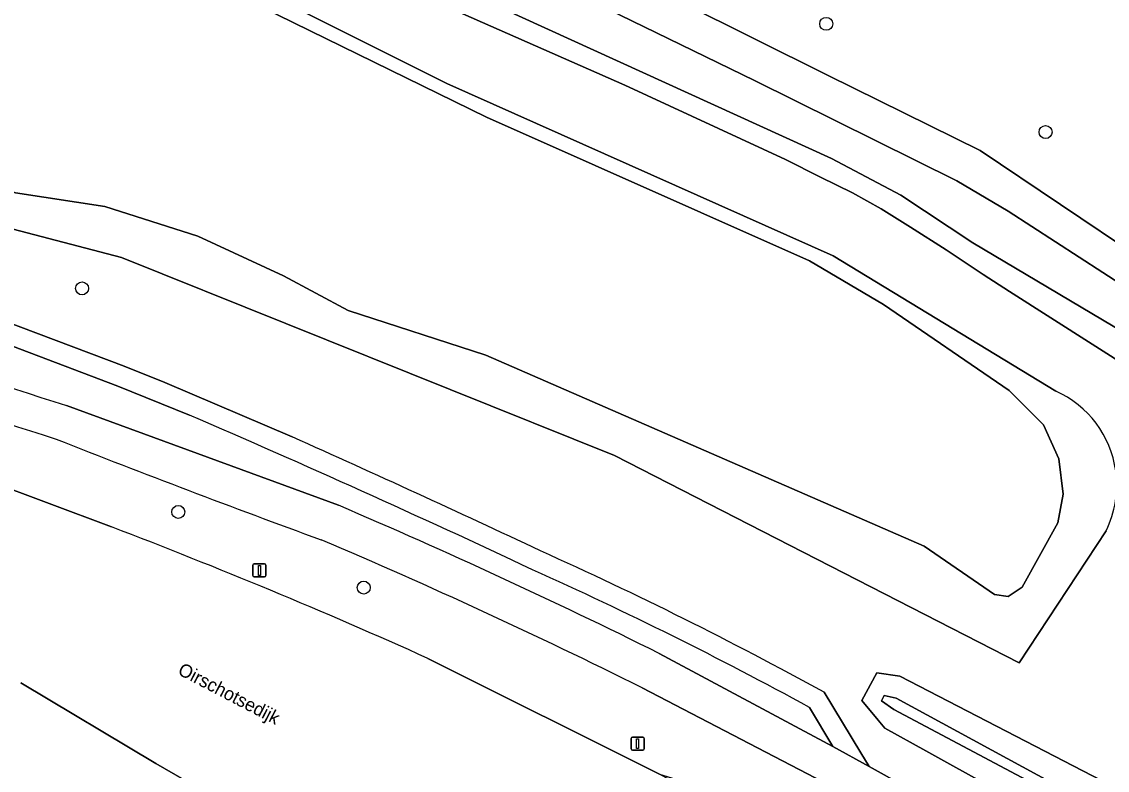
# Model space of a CAD drawing. Extents: x 156141 to 158132, y 385651 to 388333.
# Drawn here: x 157042.7 to 157124.7, y 386139.6 to 386196.1 of the extents above; entities that cross this region are included whole.
import ezdxf

# ---------------------------------------------------------------- set-up
doc = ezdxf.new("R2010")
doc.units = 0
for name, color, linetype in [('IMGEO_Berm_groen', 7, 'Continuous'), ('IMGEO_Boom', 7, 'Continuous'), ('IMGEO_Fietspad_gesloten', 7, 'Continuous'), ('IMGEO_Groenvoorziening', 7, 'Continuous'), ('IMGEO_Lichtmast', 7, 'Continuous'), ('IMGEO_Loofbos', 7, 'Continuous'), ('IMGEO_Oever', 7, 'Continuous'), ('IMGEO_Openbare_ruimte_label', 7, 'Continuous'), ('IMGEO_Rijbaan_lokaal_gesloten', 7, 'Continuous'), ('IMGEO_Voetpad_open', 7, 'Continuous'), ('IMGEO_Waterloop', 7, 'Continuous')]:
    doc.layers.add(name, color=color, linetype=linetype)

msp = doc.modelspace()

# ---------------------------------------------------------------- linework, layer by layer
at = {"layer": 'IMGEO_Berm_groen'}
for points in [[(157055.36, 386166.428), (157049.954, 386168.632), (157027.309, 386177.202)], [(157025.905, 386166.808), (157049.465, 386157.994)], [(157046.06, 386167.155), (157066.597, 386159.624)], [(157073.355, 386148.061), (157090.855, 386139.327), (157095.67, 386137.824), (157103.214, 386135.71), (157104.36, 386135.389), (157104.734, 386135.28), (157105.07, 386135.116), (157105.604, 386134.815), (157106.612, 386136.552), (157106.768, 386136.88), (157104.487, 386138.066), (157089.537, 386145.838)], [(157090.83, 386148.434), (157103.938, 386141.414), (157102.178, 386144.355)]]:
    msp.add_lwpolyline(points, dxfattribs=at)
for centre, radius, start, end in [((157167.479, 386548.294), 400.012, 247.70833, 252.32971), ((157171.751, 386565.051), 419.92, 248.03959, 252.47091), ((156726.52, 385402.107), 832.059, 64.764167, 66.72076), ((157336.91, 386902.288), 793.215, 248.428533, 249.976085), ((156888.445, 385741.984), 454.05, 63.52972, 66.89841), ((156893.257, 385748.601), 438.182, 65.73163, 69.11518), ((156888.764, 385742.679), 450.385, 63.52673, 66.92268), ((156959.162, 385882.983), 297.941, 61.31358, 65.80644)]:
    msp.add_arc(centre, radius, start, end, dxfattribs=at)
at = {"layer": 'IMGEO_Boom'}
for centre in [(157103.433, 386195.99), (157119.994, 386187.814), (157047.24, 386176.007), (157054.509, 386159.125), (157068.509, 386153.408)]:
    msp.add_circle(centre, 0.489, dxfattribs=at)
at = {"layer": 'IMGEO_Fietspad_gesloten'}
for points in [[(157066.597, 386159.624), (157046.06, 386167.155)], [(157106.669, 386139.896), (157103.938, 386141.414), (157090.83, 386148.434)], [(157089.537, 386145.838), (157104.487, 386138.066), (157106.768, 386136.88), (157129.321, 386124.103)], [(157134.922, 386123.988), (157116.672, 386134.337), (157106.669, 386139.896)]]:
    msp.add_lwpolyline(points, dxfattribs=at)
for centre, radius, start, end in [((157167.479, 386548.294), 400.012, 247.70833, 252.32971), ((157171.751, 386565.051), 419.92, 248.03959, 252.47091), ((157336.91, 386902.288), 793.215, 248.428533, 249.976085), ((156888.445, 385741.984), 454.05, 63.52972, 66.89841), ((156888.764, 385742.679), 450.385, 63.52673, 66.92268)]:
    msp.add_arc(centre, radius, start, end, dxfattribs=at)
at = {"layer": 'IMGEO_Groenvoorziening'}
for points in [[(157047.831, 386219.879), (157047.866, 386219.863), (157103.581, 386192.082), (157115.057, 386186.415), (157127.188, 386178.265), (157132.715, 386174.705), (157163.422, 386159.428)], [(157031.363, 386213.216), (157074.779, 386191.476), (157103.964, 386178.456), (157120.772, 386168.246)], [(157160.552, 386153.612), (157126.644, 386169.794), (157117.284, 386175.779), (157115.295, 386177.068), (157112.501, 386178.914), (157109.789, 386180.635), (157107.594, 386182.028), (157105.411, 386183.215), (157102.993, 386184.402), (157100.369, 386185.736), (157088.224, 386191.356), (157075.353, 386197.029)]]:
    msp.add_lwpolyline(points, dxfattribs=at)
msp.add_arc((157117.581, 386161.142), 7.788, 8.0112, 65.81079, dxfattribs=at)
at = {"layer": 'IMGEO_Lichtmast'}
for p, q in [((157060.239, 386155.211), (157061.029, 386155.211)), ((157061.029, 386155.211), (157060.239, 386155.211)), ((157060.139, 386154.311), (157060.139, 386155.111)), ((157060.139, 386155.111), (157060.139, 386154.311)), ((157061.129, 386155.111), (157061.129, 386154.311)), ((157061.129, 386154.311), (157061.129, 386155.111)), ((157061.029, 386154.211), (157060.239, 386154.211)), ((157060.239, 386154.211), (157061.029, 386154.211)), ((157088.797, 386142.12), (157089.587, 386142.12)), ((157089.587, 386142.12), (157088.797, 386142.12)), ((157088.697, 386141.22), (157088.697, 386142.02)), ((157088.697, 386142.02), (157088.697, 386141.22)), ((157089.687, 386142.02), (157089.687, 386141.22)), ((157089.687, 386141.22), (157089.687, 386142.02)), ((157089.587, 386141.12), (157088.797, 386141.12)), ((157088.797, 386141.12), (157089.587, 386141.12))]:
    msp.add_line(p, q, dxfattribs=at)
for points in [[(157060.559, 386155.086), (157060.709, 386155.086), (157060.709, 386154.336), (157060.559, 386154.336), (157060.559, 386155.086)], [(157089.117, 386141.995), (157089.267, 386141.995), (157089.267, 386141.245), (157089.117, 386141.245), (157089.117, 386141.995)]]:
    msp.add_lwpolyline(points, dxfattribs=at)
for centre, start, end in [((157060.239, 386155.111), 90, 180), ((157060.239, 386155.111), 90, 180), ((157061.029, 386155.111), 0, 90), ((157061.029, 386155.111), 360, 90), ((157060.239, 386154.311), 180, 270), ((157060.239, 386154.311), 180, 270), ((157061.029, 386154.311), 270, 0), ((157061.029, 386154.311), 270, 0), ((157088.797, 386142.02), 90, 180), ((157088.797, 386142.02), 90, 180), ((157089.587, 386142.02), 0, 90), ((157089.587, 386142.02), 360, 90), ((157088.797, 386141.22), 180, 270), ((157088.797, 386141.22), 180, 270), ((157089.587, 386141.22), 270, 0), ((157089.587, 386141.22), 270, 0)]:
    msp.add_arc(centre, 0.1, start, end, dxfattribs=at)
at = {"layer": 'IMGEO_Loofbos'}
for points in [[(157124.568, 386157.701), (157117.992, 386147.727), (157087.44, 386163.379), (157050.226, 386178.35), (157034.317, 386182.486), (157015.458, 386191.949), (157000, 386199.365), (156937.684, 386229.262), (156895.558, 386250), (156862.258, 386266.393), (156787.825, 386302.101), (156752.693, 386319.228)], [(157027.932, 386178.627), (157050.419, 386170.128), (157053.49, 386168.897), (157063.112, 386164.785)], [(157103.29, 386145.509), (157106.04, 386140.941), (157106.669, 386139.896), (157116.672, 386134.337), (157134.922, 386123.988), (157135.678, 386127.367), (157110.967, 386141.093), (157107.863, 386142.8), (157107.366, 386143.394), (157106.12, 386144.881), (157107.253, 386146.967), (157109.002, 386146.714), (157133.77, 386133.907), (157136.75, 386132.939), (157147.074, 386134.98), (157163.497, 386144.088), (157125.293, 386162.227)]]:
    msp.add_lwpolyline(points, dxfattribs=at)
for centre, radius, start, end in [((156638.121, 385213.343), 1042.046, 64.796612, 65.930582), ((157117.582, 386161.141), 7.787, 333.7823, 8.01641), ((156954.647, 385874.038), 309.501, 61.29718, 65.73109)]:
    msp.add_arc(centre, radius, start, end, dxfattribs=at)
at = {"layer": 'IMGEO_Oever'}
for points in [[(156752.693, 386319.228), (156787.825, 386302.101), (156862.258, 386266.393), (156895.558, 386250), (156937.684, 386229.262), (157000, 386199.365), (157015.458, 386191.949), (157034.317, 386182.486), (157050.226, 386178.35), (157087.44, 386163.379), (157117.992, 386147.727), (157124.568, 386157.701)], [(157006.157, 386224.026), (157077.773, 386188.944), (157102.176, 386178.077), (157107.75, 386174.799), (157117.258, 386168.288), (157119.834, 386165.712), (157121.005, 386163.136), (157121.333, 386160.466), (157120.911, 386158.312), (157118.242, 386153.44), (157117.164, 386152.738), (157116.134, 386152.878), (157110.841, 386156.532), (157077.726, 386170.958), (157067.328, 386174.33), (157062.457, 386176.953), (157055.993, 386179.951), (157048.968, 386182.199), (157042.223, 386183.23), (157036.79, 386185.197), (157030.139, 386188.007), (157000.911, 386201.778)], [(157163.422, 386159.428), (157132.715, 386174.705), (157127.188, 386178.265), (157115.057, 386186.415), (157103.581, 386192.082), (157047.866, 386219.863), (157047.831, 386219.879)], [(157120.772, 386168.246), (157103.964, 386178.456), (157074.779, 386191.476), (157031.363, 386213.216)], [(157056.353, 386212), (157098.016, 386191.719), (157113.285, 386184.131), (157117.173, 386181.836), (157129.679, 386173.733), (157130.1, 386172.843), (157129.726, 386171.86), (157128.93, 386171.579), (157127.524, 386171.719), (157114.503, 386179.447), (157109.07, 386183.054), (157103.824, 386185.817), (157078.766, 386197.246)], [(157075.353, 386197.029), (157088.224, 386191.356), (157100.369, 386185.736), (157102.993, 386184.402), (157105.411, 386183.215), (157107.594, 386182.028), (157109.789, 386180.635), (157112.501, 386178.914), (157115.295, 386177.068), (157117.284, 386175.779), (157126.644, 386169.794), (157160.552, 386153.612)]]:
    msp.add_lwpolyline(points, dxfattribs=at)
for points in [[(157170.409, 386143.435), (157169.335, 386145.238), (157168.117, 386146.206), (157167.302, 386146.245), (157163.497, 386144.088), (157147.074, 386134.98), (157136.75, 386132.939), (157133.77, 386133.907), (157109.002, 386146.714), (157107.253, 386146.967), (157106.12, 386144.881), (157107.366, 386143.394), (157107.863, 386142.8), (157110.967, 386141.093), (157135.678, 386127.367), (157138.716, 386127.281), (157141.294, 386127.765), (157147.61, 386130.326), (157152.535, 386132.451), (157165.061, 386139.441)], [(157135.881, 386129.68), (157108.546, 386144.213), (157107.619, 386144.87), (157107.819, 386145.255), (157108.715, 386145.06), (157135.91, 386130.286), (157136.359, 386130.173), (157136.793, 386130.178), (157147.95, 386132.858), (157168.428, 386144.845), (157168.797, 386144.229), (157148.037, 386132.129), (157136.7, 386129.547), (157136.254, 386129.552)]]:
    msp.add_lwpolyline(points, close=True, dxfattribs=at)
for centre, radius, start, end in [((157117.581, 386161.142), 7.788, 8.0112, 65.81079), ((157117.582, 386161.141), 7.787, 333.7823, 8.01641)]:
    msp.add_arc(centre, radius, start, end, dxfattribs=at)
at = {"layer": 'IMGEO_Rijbaan_lokaal_gesloten'}
for points in [[(157049.465, 386157.994), (157025.905, 386166.808)], [(157097.083, 386129.962), (157109.931, 386122.656), (157118.406, 386117.82), (157118.508, 386117.767), (157122.284, 386115.583), (157122.488, 386115.468), (157122.643, 386115.387), (157126.739, 386113.045), (157132.98, 386116.115), (157128.803, 386118.443), (157128.49, 386118.645), (157124.714, 386120.801), (157124.58, 386120.873), (157101.902, 386133.282), (157090.855, 386139.327), (157073.355, 386148.061)], [(157042.629, 386146.22), (157052.803, 386140.123), (157059.408, 386136.327)], [(157052.803, 386140.123), (157042.629, 386146.22)], [(157050.692, 386137.478), (157051.575, 386137.367), (157053.21, 386136.941), (157053.972, 386136.693), (157055.137, 386136.272), (157056.287, 386135.816), (157057.425, 386135.337), (157058.558, 386134.848), (157059.408, 386136.327), (157052.803, 386140.123)]]:
    msp.add_lwpolyline(points, dxfattribs=at)
msp.add_arc((156893.257, 385748.601), 438.182, 65.73163, 69.11518, dxfattribs=at)
at = {"layer": 'IMGEO_Voetpad_open'}
for points in [[(157063.112, 386164.785), (157053.49, 386168.897), (157050.419, 386170.128), (157027.932, 386178.627)], [(157027.309, 386177.202), (157049.954, 386168.632), (157055.36, 386166.428)], [(157102.178, 386144.355), (157103.938, 386141.414), (157106.669, 386139.896), (157106.04, 386140.941), (157103.29, 386145.509)]]:
    msp.add_lwpolyline(points, dxfattribs=at)
for centre, radius, start, end in [((156726.52, 385402.107), 832.059, 64.764167, 66.72076), ((156638.121, 385213.343), 1042.046, 64.796612, 65.930582), ((156954.647, 385874.038), 309.501, 61.29718, 65.73109), ((156959.162, 385882.983), 297.941, 61.31358, 65.80644)]:
    msp.add_arc(centre, radius, start, end, dxfattribs=at)
at = {"layer": 'IMGEO_Waterloop'}
for points in [[(157000.911, 386201.778), (157030.139, 386188.007), (157036.79, 386185.197), (157042.223, 386183.23), (157048.968, 386182.199), (157055.993, 386179.951), (157062.457, 386176.953), (157067.328, 386174.33), (157077.726, 386170.958), (157110.841, 386156.532), (157116.134, 386152.878), (157117.164, 386152.738), (157118.242, 386153.44), (157120.911, 386158.312), (157121.333, 386160.466), (157121.005, 386163.136), (157119.834, 386165.712), (157117.258, 386168.288), (157107.75, 386174.799), (157102.176, 386178.077), (157077.773, 386188.944), (157006.157, 386224.026)], [(157078.766, 386197.246), (157103.824, 386185.817), (157109.07, 386183.054), (157114.503, 386179.447), (157127.524, 386171.719), (157128.93, 386171.579), (157129.726, 386171.86), (157130.1, 386172.843), (157129.679, 386173.733), (157117.173, 386181.836), (157113.285, 386184.131), (157098.016, 386191.719), (157056.353, 386212)]]:
    msp.add_lwpolyline(points, dxfattribs=at)
msp.add_lwpolyline([(157136.793, 386130.178), (157136.359, 386130.173), (157135.91, 386130.286), (157108.715, 386145.06), (157107.819, 386145.255), (157107.619, 386144.87), (157108.546, 386144.213), (157135.881, 386129.68), (157136.254, 386129.552), (157136.7, 386129.547), (157148.037, 386132.129), (157168.797, 386144.229), (157168.428, 386144.845), (157147.95, 386132.858)], close=True, dxfattribs=at)

# ---------------------------------------------------------------- texts
at = {"layer": 'IMGEO_Openbare_ruimte_label'}
msp.add_text('Oirschotsedijk', height=1, rotation=332.53777, dxfattribs=at).set_placement((157054.396, 386146.899))

doc.saveas('drawing.dxf')
